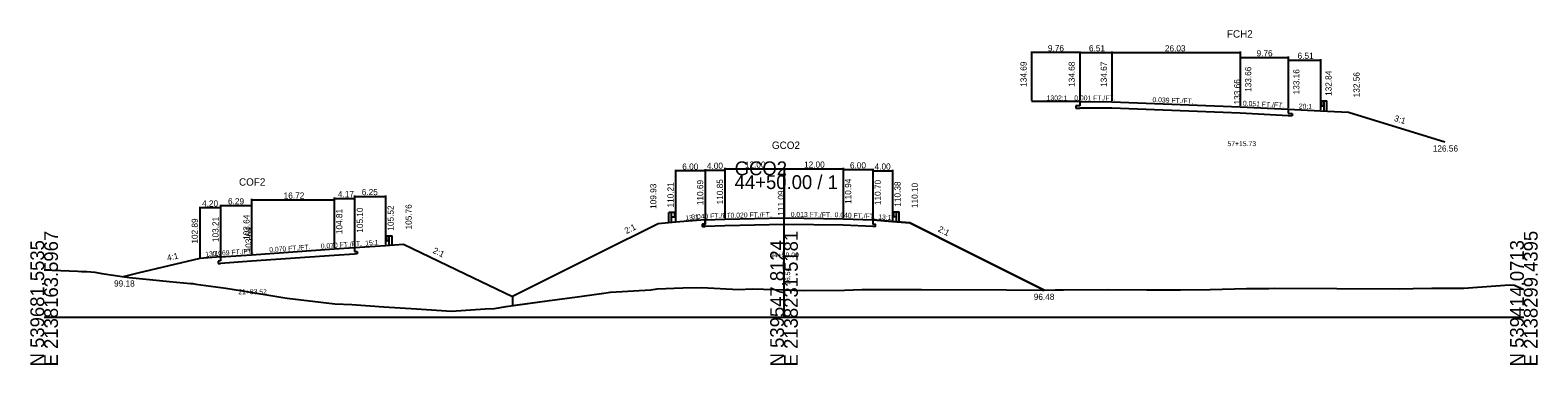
# Model space of a CAD drawing. Extents: x -14327 to 8886, y -10 to 39048.
# Drawn here: x 997.2 to 1302.8, y 28990.3 to 29058.2 of the extents above; entities that cross this region are included whole.
import ezdxf

# ---------------------------------------------------------------- set-up
doc = ezdxf.new("R2010")
doc.units = 0
for name, color, linetype in [('Level 1', 7, 'Continuous'), ('Level 20', 7, 'Continuous'), ('Level 5', 7, 'Continuous'), ('Level 53', 7, 'Continuous'), ('Level 54', 7, 'Continuous'), ('Level 55', 7, 'Continuous'), ('Level 7', 7, 'Continuous'), ('RD_GPK_XS_Cell', 7, 'Continuous'), ('RD_XS_EwShp', 7, 'Continuous'), ('RD_XS_ExGround', 7, 'Continuous'), ('RD_XS_Pave', 7, 'Continuous'), ('RD_XS_TX_Baseline', 7, 'Continuous'), ('RD_XS_TX_Elev_EX', 7, 'Continuous'), ('RD_XS_TX_Elev_PR', 7, 'Continuous'), ('RD_XS_TX_Station', 7, 'Continuous')]:
    doc.layers.add(name, color=color, linetype=linetype)

msp = doc.modelspace()

# ---------------------------------------------------------------- linework, layer by layer
at = {"layer": 'Level 1'}
for p, q in [((1126.66, 29019.21), (1126.66, 29021.2)), ((1127.22, 29021.2), (1126.66, 29021.2)), ((1127.22, 29019.21), (1127.22, 29021.2)), ((1127.77, 29021.2), (1127.22, 29021.2)), ((1127.77, 29020.23), (1127.22, 29020.23)), ((1127.77, 29021.2), (1127.77, 29020.23)), ((1127.85, 29021.13), (1127.77, 29021.14)), ((1127.85, 29020.3), (1127.77, 29020.29)), ((1127.84, 29020.79), (1127.84, 29020.64)), ((1127.98, 29021.03), (1127.86, 29021.12)), ((1127.98, 29020.93), (1127.86, 29020.84)), ((1127.98, 29020.5), (1127.86, 29020.59)), ((1127.98, 29020.4), (1127.86, 29020.31)), ((1172.02, 29021.2), (1172.14, 29021.29)), ((1172.02, 29021.1), (1172.14, 29021)), ((1172.02, 29020.67), (1172.14, 29020.76)), ((1172.02, 29020.57), (1172.14, 29020.48)), ((1172.15, 29021.29), (1172.23, 29021.31)), ((1172.15, 29020.47), (1172.23, 29020.46)), ((1172.16, 29020.96), (1172.16, 29020.8)), ((1172.23, 29021.37), (1172.23, 29020.4)), ((1172.23, 29021.37), (1172.78, 29021.37)), ((1172.23, 29020.4), (1172.78, 29020.4)), ((1172.78, 29019.38), (1172.78, 29021.37)), ((1172.78, 29021.37), (1173.34, 29021.37)), ((1173.34, 29019.38), (1173.34, 29021.37))]:
    msp.add_line(p, q, dxfattribs=at)
for centre, radius, start, end in [((1127.91, 29020.79), 0.0651, 135, 180), ((1127.91, 29020.64), 0.0651, 180, 237.0105), ((1127.85, 29021.1), 0.026, 50.9495, 90), ((1127.85, 29020.33), 0.026, 270, 309.0504), ((1127.93, 29020.98), 0.0651, 309.0337, 50.9664), ((1127.93, 29020.45), 0.0651, 309.0337, 50.9664), ((1172.07, 29021.15), 0.0651, 129.0336, 230.9663), ((1172.07, 29020.62), 0.0651, 129.0336, 230.9663), ((1172.09, 29020.8), 0.0651, 302.9895, 0), ((1172.15, 29021.27), 0.026, 90, 129.0505), ((1172.09, 29020.96), 0.0651, 0, 45), ((1172.15, 29020.5), 0.026, 230.9496, 270)]:
    msp.add_arc(centre, radius, start, end, dxfattribs=at)
at = {"layer": 'Level 20'}
for p, q in [((1200.19, 29053.84), (1200.19, 29043.89)), ((1209.95, 29053.64), (1200.19, 29053.64)), ((1209.95, 29053.84), (1209.95, 29043.88)), ((1209.95, 29053.83), (1209.95, 29043.88)), ((1209.95, 29053.63), (1216.46, 29053.63)), ((1216.46, 29053.83), (1216.46, 29043.87)), ((1216.46, 29053.82), (1216.46, 29043.87)), ((1216.46, 29053.62), (1242.49, 29053.62)), ((1242.49, 29053.82), (1242.49, 29042.86)), ((1242.49, 29052.81), (1242.49, 29042.86)), ((1242.49, 29052.61), (1252.25, 29052.61)), ((1252.25, 29052.81), (1252.25, 29042.36)), ((1252.25, 29052.31), (1252.25, 29042.36)), ((1252.25, 29052.11), (1258.76, 29052.11)), ((1258.76, 29052.31), (1258.76, 29042.04)), ((1209.95, 29043.68), (1200.19, 29043.69)), ((1209.14, 29042.85), (1209.14, 29042.35)), ((1209.95, 29042.84), (1209.14, 29042.85)), ((1209.95, 29043.68), (1209.95, 29042.84)), ((1209.95, 29043.68), (1216.46, 29043.67)), ((1216.46, 29043.67), (1242.49, 29042.66)), ((1258.78, 29043.65), (1258.89, 29043.74)), ((1258.78, 29043.55), (1258.89, 29043.46)), ((1258.78, 29043.12), (1258.89, 29043.21)), ((1258.78, 29043.02), (1258.89, 29042.93)), ((1258.91, 29043.75), (1258.98, 29043.76)), ((1258.91, 29043.41), (1258.91, 29043.26)), ((1258.91, 29042.92), (1258.98, 29042.91)), ((1258.98, 29043.82), (1258.98, 29042.85)), ((1258.98, 29043.82), (1259.54, 29043.82)), ((1258.98, 29042.85), (1259.54, 29042.85)), ((1259.54, 29041.84), (1259.54, 29043.82)), ((1259.54, 29043.82), (1260.09, 29043.82)), ((1260.09, 29041.84), (1260.09, 29043.82)), ((1209.14, 29042.35), (1209.95, 29042.34)), ((1216.46, 29042.34), (1209.95, 29042.34)), ((1242.49, 29041.32), (1216.46, 29042.34)), ((1242.49, 29042.66), (1252.25, 29042.16)), ((1252.25, 29040.82), (1242.49, 29041.32)), ((1252.25, 29042.16), (1252.25, 29041.32)), ((1252.25, 29042.16), (1258.76, 29041.84)), ((1252.25, 29041.32), (1253.06, 29041.3)), ((1253.06, 29040.8), (1252.25, 29040.82)), ((1253.06, 29041.3), (1253.06, 29040.8)), ((1258.76, 29041.84), (1264.45, 29041.56)), ((1264.45, 29041.56), (1283.97, 29035.56)), ((1062.95, 29024.67), (1062.95, 29014.3)), ((1062.95, 29024.47), (1069.2, 29024.47)), ((1069.2, 29024.67), (1069.2, 29014.72)), ((1031.58, 29022.36), (1031.58, 29012.09)), ((1035.77, 29022.16), (1031.58, 29022.16)), ((1035.77, 29022.79), (1035.77, 29012.41)), ((1035.77, 29022.59), (1042.06, 29022.59)), ((1035.77, 29022.36), (1035.77, 29012.41)), ((1042.06, 29023.96), (1042.06, 29012.84)), ((1042.06, 29023.76), (1058.78, 29023.76)), ((1042.06, 29022.79), (1042.06, 29012.84)), ((1058.78, 29024.25), (1058.78, 29014.01)), ((1058.78, 29024.05), (1062.95, 29024.05)), ((1058.78, 29023.96), (1058.78, 29014.01)), ((1062.95, 29024.25), (1062.95, 29014.3)), ((1069.22, 29016.33), (1069.34, 29016.42)), ((1069.22, 29016.23), (1069.34, 29016.14)), ((1069.22, 29015.8), (1069.34, 29015.89)), ((1069.22, 29015.7), (1069.34, 29015.61)), ((1069.35, 29016.43), (1069.43, 29016.44)), ((1069.35, 29015.6), (1069.43, 29015.59)), ((1069.36, 29016.09), (1069.36, 29015.94)), ((1069.43, 29016.5), (1069.43, 29015.53)), ((1069.43, 29016.5), (1069.98, 29016.5)), ((1069.43, 29015.53), (1069.98, 29015.53)), ((1069.98, 29014.52), (1069.98, 29016.5)), ((1069.98, 29016.5), (1070.54, 29016.5)), ((1070.54, 29014.52), (1070.54, 29016.5)), ((1035.77, 29012.21), (1042.06, 29012.64)), ((1042.06, 29012.64), (1058.78, 29013.81)), ((1058.78, 29012.47), (1042.06, 29011.31)), ((1058.78, 29013.81), (1062.95, 29014.1)), ((1062.95, 29012.76), (1058.78, 29012.47)), ((1062.95, 29014.1), (1069.2, 29014.52)), ((1062.95, 29014.1), (1062.95, 29013.26)), ((1062.95, 29013.26), (1063.47, 29013.3)), ((1063.47, 29012.8), (1062.95, 29012.76)), ((1063.47, 29013.3), (1063.47, 29012.8)), ((1069.2, 29014.52), (1072.84, 29014.76)), ((1072.84, 29014.76), (1085.34, 29008.76)), ((1031.58, 29011.89), (1018.99, 29008.89)), ((1035.77, 29012.21), (1031.58, 29011.89)), ((1035.77, 29011.37), (1035.25, 29011.34)), ((1035.25, 29011.34), (1035.25, 29010.84)), ((1035.25, 29010.84), (1035.77, 29010.87)), ((1035.77, 29012.21), (1035.77, 29011.37)), ((1042.06, 29011.31), (1035.77, 29010.87)), ((1018.99, 29008.89), (1016.02, 29008.18)), ((1085.34, 29008.76), (1094.94, 29004.15))]:
    msp.add_line(p, q, dxfattribs=at)
for centre, radius, start, end in [((1258.82, 29043.6), 0.0651, 129.0336, 230.9663), ((1258.82, 29043.07), 0.0651, 129.0336, 230.9663), ((1258.85, 29043.26), 0.0651, 302.9895, 0), ((1258.91, 29043.72), 0.026, 90, 129.0505), ((1258.85, 29043.41), 0.0651, 0, 45), ((1258.91, 29042.95), 0.026, 230.9496, 270), ((1069.26, 29016.28), 0.0651, 129.0336, 230.9663), ((1069.26, 29015.75), 0.0651, 129.0336, 230.9663), ((1069.29, 29015.94), 0.0651, 302.9895, 0), ((1069.35, 29016.4), 0.026, 90, 129.0505), ((1069.29, 29016.09), 0.0651, 0, 45), ((1069.35, 29015.63), 0.026, 230.9496, 270)]:
    msp.add_arc(centre, radius, start, end, dxfattribs=at)
at = {"layer": 'Level 5'}
for p, q in [((1134, 29018.86), (1133.5, 29018.84)), ((1133.5, 29018.84), (1133.5, 29018.34)), ((1133.5, 29018.34), (1134, 29018.36)), ((1134, 29019.69), (1134, 29018.86)), ((1138, 29018.52), (1134, 29018.36)), ((1150, 29018.76), (1138, 29018.52)), ((1162, 29018.61), (1150, 29018.76)), ((1168, 29018.37), (1162, 29018.61)), ((1168, 29019.7), (1168, 29018.87)), ((1168, 29018.87), (1168.5, 29018.85)), ((1168.5, 29018.35), (1168, 29018.37)), ((1168.5, 29018.85), (1168.5, 29018.35))]:
    msp.add_line(p, q, dxfattribs=at)
at = {"layer": 'Level 54'}
for p, q in [((1128, 29029.84), (1128, 29019.41)), ((1134, 29029.64), (1128, 29029.64)), ((1134, 29030), (1134, 29019.89)), ((1134, 29029.84), (1134, 29019.89)), ((1134, 29029.8), (1138, 29029.8)), ((1138, 29030.24), (1138, 29020.05)), ((1138, 29030.04), (1150, 29030.04)), ((1138, 29030), (1138, 29020.05)), ((1150, 29030.24), (1150, 29020.29)), ((1150, 29030.04), (1162, 29030.04)), ((1162, 29030.24), (1162, 29020.14)), ((1162, 29030.09), (1162, 29020.14)), ((1162, 29029.89), (1168, 29029.89)), ((1168, 29030.09), (1168, 29019.9)), ((1168, 29029.85), (1168, 29019.9)), ((1168, 29029.65), (1172, 29029.65)), ((1172, 29029.85), (1172, 29019.58))]:
    msp.add_line(p, q, dxfattribs=at)
at = {"layer": 'Level 7'}
for p, q in [((1124.5, 29018.93), (1112.5, 29012.93)), ((1128, 29019.21), (1124.5, 29018.93)), ((1134, 29019.69), (1128, 29019.21)), ((1168, 29019.7), (1172, 29019.38)), ((1172, 29019.38), (1175.5, 29019.1)), ((1175.5, 29019.1), (1187.5, 29013.1)), ((1112.5, 29012.93), (1094.94, 29004.15)), ((1187.5, 29013.1), (1202.75, 29005.48)), ((1094.94, 29004.15), (1094.94, 29002.33))]:
    msp.add_line(p, q, dxfattribs=at)
at = {"layer": 'RD_GPK_XS_Cell'}
for p, q in [((1150, 29000), (1150, 29028.76)), ((1000, 29000), (1150, 29000)), ((1150, 29000), (1300, 29000))]:
    msp.add_line(p, q, dxfattribs=at)
at = {"layer": 'RD_XS_EwShp'}
msp.add_lwpolyline([(1094.94, 29004.15), (1094.94, 29002.33), (1102.46, 29003.39), (1107.56, 29004.04), (1113.01, 29004.8), (1114.82, 29005.05), (1122.99, 29005.53), (1124.28, 29005.75), (1129.49, 29005.94), (1133.35, 29006.02), (1140.76, 29005.58), (1143.53, 29005.73), (1148.14, 29005.62), (1150, 29005.54), (1154.08, 29005.37), (1162.26, 29005.48), (1165.78, 29005.57), (1171.38, 29005.59), (1174.74, 29005.59), (1177.91, 29005.61), (1195.12, 29005.54), (1202.38, 29005.47), (1202.75, 29005.48), (1187.5, 29013.1), (1175.5, 29019.1), (1172, 29019.38), (1168, 29019.7), (1168, 29018.87), (1168.5, 29018.85), (1168.5, 29018.35), (1168, 29018.37), (1162, 29018.61), (1150, 29018.76), (1138, 29018.52), (1134, 29018.36), (1133.5, 29018.34), (1133.5, 29018.84), (1134, 29018.86), (1134, 29019.69), (1128, 29019.21), (1124.5, 29018.93), (1112.5, 29012.93)], close=True, dxfattribs=at)
at = {"layer": 'RD_XS_ExGround'}
for p, q in [((1000, 29009.59), (1001.62, 29009.51)), ((1001.62, 29009.51), (1006.83, 29009.31)), ((1006.83, 29009.31), (1007.58, 29009.27)), ((1007.58, 29009.27), (1008.66, 29009.21)), ((1008.66, 29009.21), (1010.27, 29009.07)), ((1010.27, 29009.07), (1011.7, 29008.85)), ((1011.7, 29008.85), (1015.78, 29008.21)), ((1015.78, 29008.21), (1017.29, 29008.03)), ((1017.29, 29008.03), (1025.41, 29007.21)), ((1025.41, 29007.21), (1029.67, 29006.79)), ((1029.67, 29006.79), (1030.15, 29006.8)), ((1030.15, 29006.8), (1030.74, 29006.65)), ((1030.74, 29006.65), (1036.82, 29005.83)), ((1287.81, 29005.86), (1297.06, 29006.52)), ((1297.06, 29006.52), (1298.14, 29006.49)), ((1298.14, 29006.49), (1300, 29005.61)), ((1036.82, 29005.83), (1040.24, 29005.34)), ((1040.24, 29005.34), (1048.36, 29003.96)), ((1048.36, 29003.96), (1049.3, 29003.86)), ((1049.3, 29003.86), (1058.93, 29002.71)), ((1093.69, 29002.16), (1102.46, 29003.39)), ((1102.46, 29003.39), (1107.56, 29004.04)), ((1107.56, 29004.04), (1113.01, 29004.8)), ((1113.01, 29004.8), (1114.82, 29005.05)), ((1114.82, 29005.05), (1122.99, 29005.53)), ((1122.99, 29005.53), (1124.28, 29005.75)), ((1124.28, 29005.75), (1129.49, 29005.94)), ((1129.49, 29005.94), (1133.35, 29006.02)), ((1133.35, 29006.02), (1140.76, 29005.58)), ((1140.76, 29005.58), (1143.53, 29005.73)), ((1143.53, 29005.73), (1148.14, 29005.62)), ((1148.14, 29005.62), (1150, 29005.54)), ((1150, 29005.54), (1154.08, 29005.37)), ((1154.08, 29005.37), (1162.26, 29005.48)), ((1162.26, 29005.48), (1165.78, 29005.57)), ((1165.78, 29005.57), (1171.38, 29005.59)), ((1171.38, 29005.59), (1174.74, 29005.59)), ((1174.74, 29005.59), (1177.91, 29005.61)), ((1177.91, 29005.61), (1195.12, 29005.54)), ((1195.12, 29005.54), (1202.38, 29005.47)), ((1202.38, 29005.47), (1205, 29005.51)), ((1205, 29005.51), (1206.67, 29005.53)), ((1206.67, 29005.53), (1215.88, 29005.57)), ((1215.88, 29005.57), (1223.56, 29005.55)), ((1223.56, 29005.55), (1230.39, 29005.55)), ((1230.39, 29005.55), (1236.39, 29005.6)), ((1236.39, 29005.6), (1243.76, 29005.78)), ((1243.76, 29005.78), (1248.27, 29005.81)), ((1248.27, 29005.81), (1249.42, 29005.84)), ((1249.42, 29005.84), (1274.75, 29005.71)), ((1274.75, 29005.71), (1277.53, 29005.8)), ((1277.53, 29005.8), (1281.36, 29005.88)), ((1281.36, 29005.88), (1287.81, 29005.86)), ((1058.93, 29002.71), (1062.4, 29002.54)), ((1062.4, 29002.54), (1068.85, 29002.04)), ((1068.85, 29002.04), (1075.49, 29001.67)), ((1075.49, 29001.67), (1082.61, 29001.17)), ((1082.61, 29001.17), (1089.44, 29001.66)), ((1089.44, 29001.66), (1091.3, 29001.76)), ((1091.3, 29001.76), (1093.69, 29002.16))]:
    msp.add_line(p, q, dxfattribs=at)
at = {"layer": 'RD_XS_Pave'}
for p, q in [((1134, 29019.69), (1138, 29019.85)), ((1138, 29019.85), (1150, 29020.09)), ((1150, 29020.09), (1162, 29019.94)), ((1162, 29019.94), (1168, 29019.7))]:
    msp.add_line(p, q, dxfattribs=at)

# ---------------------------------------------------------------- texts
at = {"layer": 'Level 20'}
for s, height, p in [('FCH2', 1.5, (1239.8, 29056.66)), ('9.76', 1.25, (1203.51, 29053.89)), ('6.51', 1.25, (1211.83, 29053.88)), ('26.03', 1.25, (1227.23, 29053.87)), ('9.76', 1.25, (1245.81, 29052.86)), ('6.51', 1.25, (1254.13, 29052.36)), ('57+15.73', 1, (1239.91, 29034.66)), ('126.56', 1.25, (1281.54, 29033.56)), ('COF2', 1.5, (1039.5, 29026.64)), ('16.72', 1.25, (1048.56, 29024.01)), ('4.17', 1.25, (1059.56, 29024.3)), ('6.25', 1.25, (1064.39, 29024.72)), ('4.20', 1.25, (1032.01, 29022.41)), ('6.29', 1.25, (1037.27, 29022.84)), ('99.18', 1.25, (1014.17, 29006.18)), ('21+83.52', 1, (1039.36, 29004.64))]:
    msp.add_text(s, height=height, dxfattribs=at).set_placement(p)
for s, height, rotation, p in [('134.69', 1.25, 90, (1199.19, 29046.69)), ('134.68', 1.25, 90, (1208.95, 29046.68)), ('134.67', 1.25, 90, (1215.46, 29046.67)), ('133.66', 1.25, 90, (1244.74, 29045.66)), ('133.16', 1.25, 90, (1254.5, 29045.16)), ('132.84', 1.25, 90, (1261.01, 29044.84)), ('132.56', 1.25, 90, (1266.7, 29044.56)), (' 133.66', 1.25, 90, (1242.49, 29042.66)), ('1302:1', 1, 359.956, (1203.25, 29043.93)), ('0.001 FT./FT.', 1, 359.9284, (1208.85, 29043.93)), ('0.039 FT./FT.', 1, 357.7713, (1224.69, 29043.6)), ('0.051 FT./FT.', 1, 357.0573, (1243.02, 29042.88)), ('20:1', 1, 357.1848, (1254.35, 29042.3)), ('3:1', 1.25, 342.9157, (1273.6, 29039.79)), ('104.81', 1.25, 90, (1060.45, 29016.81)), ('105.10', 1.25, 90, (1064.62, 29017.1)), ('105.52', 1.25, 90, (1070.87, 29017.52)), ('105.76', 1.25, 90, (1074.51, 29017.76)), ('102.89', 1.25, 90, (1031.15, 29014.89)), ('103.21', 1.25, 90, (1035.35, 29015.21)), ('103.64', 1.25, 90, (1041.64, 29015.64)), (' 103.64', 1.25, 90, (1042.06, 29012.64)), ('0.070 FT./FT.', 1, 3.9961, (1056.11, 29013.87)), ('15:1', 1, 3.8375, (1065.13, 29014.49)), ('4:1', 1.25, 13.4008, (1025.05, 29011.36)), ('13:1', 1, 4.3598, (1032.7, 29012.22)), ('0.069 FT./FT.', 1, 3.9626, (1034.17, 29012.35)), ('0.070 FT./FT.', 1, 3.9808, (1045.67, 29013.14)), ('2:1', 1.25, 334.355, (1078.68, 29013.07))]:
    msp.add_text(s, height=height, rotation=rotation, dxfattribs=at).set_placement(p)
at = {"layer": 'Level 53'}
for s, rotation, p in [('110.69', 90, (1133.62, 29022.69)), ('110.85', 90, (1137.63, 29022.85)), ('110.94', 90, (1163.62, 29022.94)), ('110.70', 90, (1169.63, 29022.7)), ('109.93', 90, (1124.12, 29021.93)), ('110.21', 90, (1127.62, 29022.21)), ('110.38', 90, (1173.63, 29022.38)), ('110.10', 90, (1177.13, 29022.1)), ('2:1', 26.5651, (1118.05, 29016.83)), ('2:1', 333.4349, (1181.11, 29017.42))]:
    msp.add_text(s, height=1.25, rotation=rotation, dxfattribs=at).set_placement(p)
msp.add_text('96.48', height=1.25, dxfattribs=at).set_placement((1200.64, 29003.48))
at = {"layer": 'Level 54'}
for s, p in [('6.00', (1129.37, 29029.89)), ('4.00', (1134.37, 29030.05)), ('12.00', (1142.07, 29030.29)), ('12.00', (1154.07, 29030.29)), ('6.00', (1163.37, 29030.14)), ('4.00', (1168.37, 29029.9))]:
    msp.add_text(s, height=1.25, dxfattribs=at).set_placement(p)
at = {"layer": 'Level 55'}
for s, rotation, p in [('13:1', 4.5739, (1130.03, 29019.62)), ('0.040 FT./FT.', 2.2906, (1131.22, 29019.83)), ('0.020 FT./FT.', 1.1458, (1139.17, 29020.13)), ('0.013 FT./FT.', 359.2788, (1151.35, 29020.32)), ('0.040 FT./FT.', 357.7094, (1160.24, 29020.26)), ('13:1', 355.4261, (1169.07, 29019.87))]:
    msp.add_text(s, height=1, rotation=rotation, dxfattribs=at).set_placement(p)
at = {"layer": 'RD_GPK_XS_Cell'}
for s, p in [('GCO2', (1140, 29028.76)), ('44+50.00 / 1', (1140, 29025.96))]:
    msp.add_text(s, height=2.8, dxfattribs=at).set_placement(p)
for s, p in [('N 539681.5535', (1000, 28990)), ('E 2138163.5967', (1002.8, 28990)), ('N 539547.8124', (1150, 28990)), ('E 2138231.5181', (1152.8, 28990)), ('N 539414.0713', (1300, 28990)), ('E 2138299.4395', (1302.8, 28990))]:
    msp.add_text(s, height=2.8, rotation=90, dxfattribs=at).set_placement(p)
at = {"layer": 'RD_XS_TX_Baseline'}
msp.add_text('GCO2', height=1.5, dxfattribs=at).set_placement((1147.55, 29034.09))
at = {"layer": 'RD_XS_TX_Elev_EX'}
msp.add_text('96.54', height=1, rotation=90, dxfattribs=at).set_placement((1151.25, 29006.54))
at = {"layer": 'RD_XS_TX_Elev_PR'}
msp.add_text(' 111.09', height=1.25, rotation=90, dxfattribs=at).set_placement((1150, 29020.09))
at = {"layer": 'RD_XS_TX_Station'}
msp.add_text('44+50.00', height=1, dxfattribs=at).set_placement((1147.21, 29012.09))

doc.saveas('drawing.dxf')
